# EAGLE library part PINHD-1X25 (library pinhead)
PIN HEADER
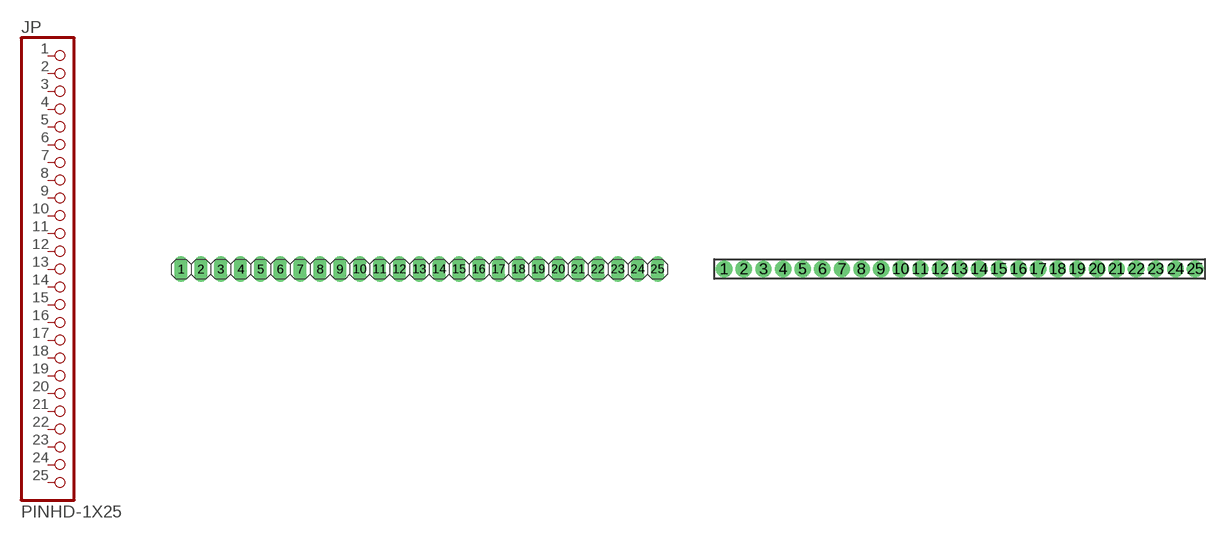
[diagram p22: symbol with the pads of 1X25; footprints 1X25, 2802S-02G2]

Designator prefix JP

## PINHD-1X25  [1X25]
1  1  pas
2  2  pas
3  3  pas
4  4  pas
5  5  pas
6  6  pas
7  7  pas
8  8  pas
9  9  pas
10  10  pas
11  11  pas
12  12  pas
13  13  pas
14  14  pas
15  15  pas
16  16  pas
17  17  pas
18  18  pas
19  19  pas
20  20  pas
21  21  pas
22  22  pas
23  23  pas
24  24  pas
25  25  pas

## PINHD-1X25_2802S-02G2  [2802S-02G2]
Pads as for 1X25

## Footprint 1X25 (pad centres in mm)
PIN HEADER
drill 1.016 pad 1.67 long: 1 -29.21,0; 2 -26.67,0; 3 -24.13,0; 4 -21.59,0; 5 -19.05,0; 6 -16.51,0; 7 -13.97,0; 8 -11.43,0; 9 -8.89,0; 10 -6.35,0; 11 -3.81,0; 12 -1.27,0; 13 1.27,0; 14 3.81,0; 15 6.35,0; 16 8.89,0; 17 11.43,0; 18 13.97,0; 19 16.51,0; 20 19.05,0; 21 21.59,0; 22 24.13,0; 23 26.67,0; 24 29.21,0; 25 31.75,0

## Footprint 2802S-02G2 (pad centres in mm)
2mm Center - .020 inch Square Pin - Single Row Straight Header Source: http://www.commcon.com/main
drill 0.8 pad 1.67 round: 1 -24,0; 2 -22,0; 3 -20,0; 4 -18,0; 5 -16,0; 6 -14,0; 7 -12,0; 8 -10,0; 9 -8,0; 10 -6,0; 11 -4,0; 12 -2,0; 13 0,0; 14 2,0; 15 4,0; 16 6,0; 17 8,0; 18 10,0; 19 12,0; 20 14,0; 21 16,0; 22 18,0; 23 20,0; 24 22,0; 25 24,0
